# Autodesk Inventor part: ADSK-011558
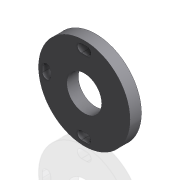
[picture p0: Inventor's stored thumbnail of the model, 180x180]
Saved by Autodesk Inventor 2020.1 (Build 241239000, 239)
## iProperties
Created: 2000-02
Part Number: ADSK-011558
Material: Pearson HRS
Document SubType Name: Modeling
Designer: sspink
Density: 7.83 g/cm^3
Appearance: Métal - Acier
Mass: 622.587 g
Surface Area: 196.555 cm^2
Volume: 79.513 cm^3
Control State: 0
Checked Out: False
Master: False
Shininess: 0.0
Length Units: 11269
Angle Units: 11279
Time Units: 11290
Mass Units: 11283
Length Display Precision: 3
Angle Display Precision: 2
Compacted: True
Dimensions: 100x12,5x100 mm
Mass: 0,623 kg
VLT_Material: Pearson HRS
Density: 0.0
Volumn: 0.0
Area: 0.0
PropertySet Name: Model Information
Author: sspink
Revision Number: -
Title: ADSK-011558
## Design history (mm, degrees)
node "Circular Pattern1" dims "d10" = 30, "d12" = 90 deg
node "Solide1"
  node "Extrusion1" dims "d1" = 12.5, "d2" = 0
  node "Extrusion2" dims "d8" = 12.7, "d9" = 0
sketch "Sketch1"
  geometry: C1 r 50 at (0, 0); C2 r 19.05 at (0, 0) reference; 1 further point
  constraints: 1 centre point, 1 coincident
  dimensions: "d0" = 100 diameter of C1
sketch "Sketch2"
  geometry: L1 (0, 0)-(0, 50); L2 (0, 0)-(-50, 0); L3 (0, 0)-(0, -50); L4 (0, 41.25)-(3, 41.25); L5 (0, 41.25)-(-3, 41.25); L6 (-3, 45.75)-(3, 45.75); L7 (-3, 36.75)-(3, 36.75); A1 r 50 centre (0, 0) between (0, 50) and (-50, 0) reference; A2 r 41.25 centre (0, 0) between (0, 41.25) and (-2.039, 41.2); A3 r 5.039 centre (3, 41.25) between (-2.039, 41.25) and (-2.039, 41.2); A4 r 4.5 centre (3, 41.25) between (3, 36.75) and (3, 45.75); A5 r 4.5 centre (-3, 41.25) between (-3, 45.75) and (-3, 36.75); A6 r 5.039 centre (-3, 41.25) between (2.039, 41.2) and (2.039, 41.25)
  constraints: 14 end point, 14 point on circle, 6 tangent, 5 centre point, 3 coincident, 3 point on line, 2 perpendicular, 1 collinear, 1 vertical
  dimensions: "d3" = 82.5 diameter of A2; "d4" = 3 distance of L4.start L5.end; "d6" = 4.5 radius of A4; "d7" = 4.5 radius of A5 (= d6)
node "Corps solides"
node "Corps surfaciques"
other parameters: "d5" = 10.3124
